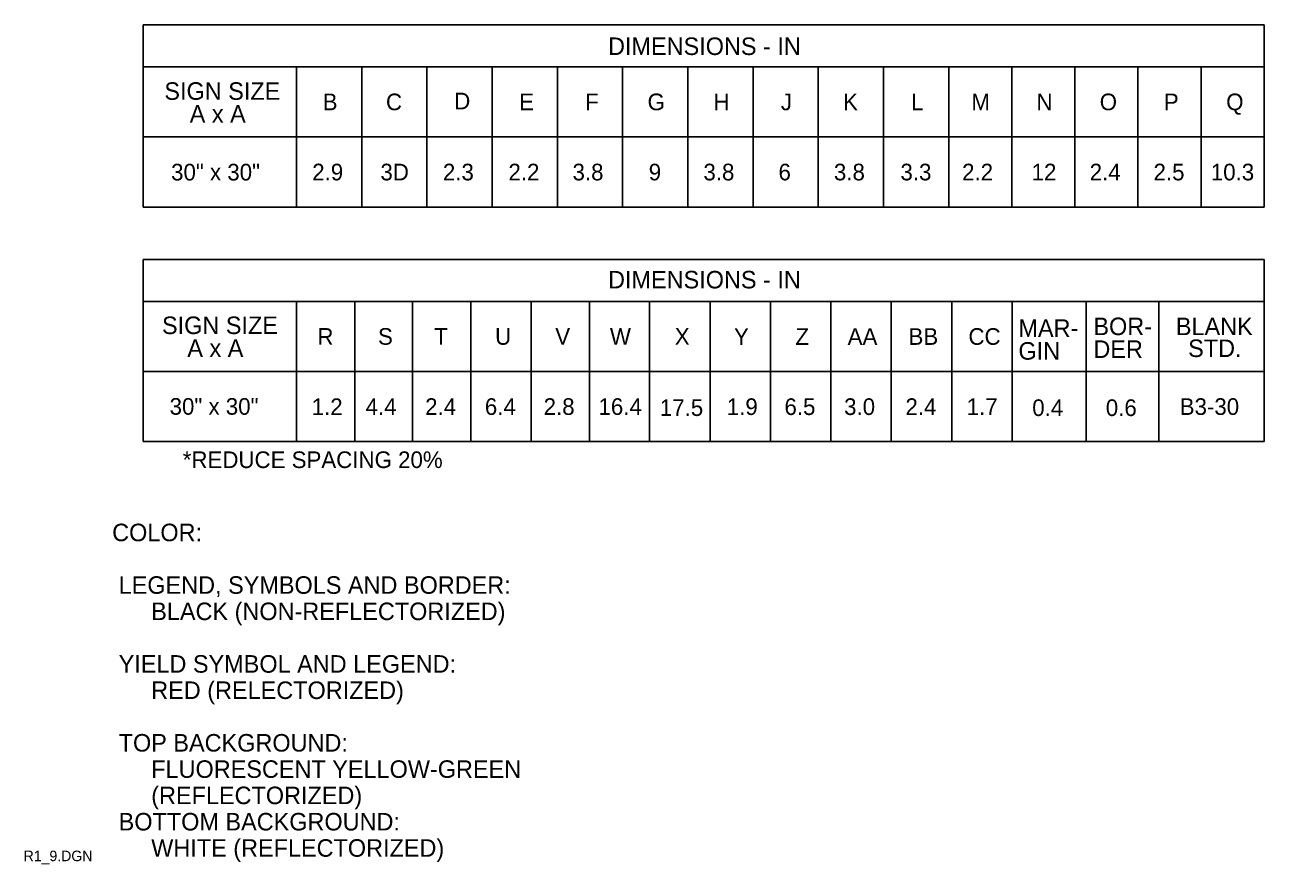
# Model space of a CAD drawing. Extents: x 0.013 to 0.193, y 0.003 to 0.259.
# Drawn here: x 0.0127 to 0.1894, y 0.0028 to 0.1225 of the extents above; entities that cross this region are included whole.
import ezdxf

# ---------------------------------------------------------------- set-up
doc = ezdxf.new("R2010")
doc.units = 0
doc.layers.add('1', color=7, linetype='Continuous')
doc.layers.add('3', color=7, linetype='Continuous')

msp = doc.modelspace()

# ---------------------------------------------------------------- linework, layer by layer
at = {"layer": '3'}
for p, q in [((0.02954535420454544, 0.12249248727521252), (0.02954535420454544, 0.09649248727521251)), ((0.02954535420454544, 0.1224891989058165), (0.1894203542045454, 0.1224891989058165)), ((0.1894203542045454, 0.12249248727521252), (0.1894203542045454, 0.09649248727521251)), ((0.02954535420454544, 0.1164891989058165), (0.1894203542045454, 0.1164891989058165)), ((0.05142035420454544, 0.1164891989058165), (0.05142035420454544, 0.09649248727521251)), ((0.06072035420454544, 0.1164891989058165), (0.06072035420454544, 0.09649248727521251)), ((0.07002035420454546, 0.1164891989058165), (0.07002035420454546, 0.09649248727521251)), ((0.07932035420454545, 0.1164891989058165), (0.07932035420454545, 0.09649248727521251)), ((0.08862035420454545, 0.1164891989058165), (0.08862035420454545, 0.09649248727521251)), ((0.09792035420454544, 0.1164891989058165), (0.09792035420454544, 0.09649248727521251)), ((0.10722035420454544, 0.1164891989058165), (0.10722035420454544, 0.09649248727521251)), ((0.11652035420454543, 0.1164891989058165), (0.11652035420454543, 0.09649248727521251)), ((0.12582035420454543, 0.1164891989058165), (0.12582035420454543, 0.09649248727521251)), ((0.13512035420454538, 0.1164891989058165), (0.13512035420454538, 0.09649248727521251)), ((0.14442035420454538, 0.1164891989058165), (0.14442035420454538, 0.09649248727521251)), ((0.1534203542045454, 0.1164891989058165), (0.1534203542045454, 0.09649248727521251)), ((0.1624203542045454, 0.1164891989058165), (0.1624203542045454, 0.09649248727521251)), ((0.1714203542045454, 0.1164891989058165), (0.1714203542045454, 0.09649248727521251)), ((0.18042035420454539, 0.1164891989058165), (0.18042035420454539, 0.09649248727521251)), ((0.02954535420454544, 0.10649248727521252), (0.1894203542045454, 0.10649248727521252)), ((0.02954535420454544, 0.09649248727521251), (0.1894203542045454, 0.09649248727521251)), ((0.02954535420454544, 0.08904164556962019), (0.02954535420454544, 0.06304493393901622)), ((0.02954535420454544, 0.08904164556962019), (0.1894203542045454, 0.08904164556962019)), ((0.1894203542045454, 0.06304493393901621), (0.1894203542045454, 0.08904164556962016)), ((0.029545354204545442, 0.08304164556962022), (0.1894203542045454, 0.08304164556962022)), ((0.051420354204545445, 0.08304164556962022), (0.051420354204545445, 0.06304493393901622)), ((0.05972318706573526, 0.08304164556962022), (0.05972318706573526, 0.06304493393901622)), ((0.06795264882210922, 0.08304164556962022), (0.06795264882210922, 0.06304493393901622)), ((0.07627276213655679, 0.08304164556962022), (0.07627276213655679, 0.06304493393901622)), ((0.08486483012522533, 0.08304164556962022), (0.08486483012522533, 0.06304493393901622)), ((0.09318494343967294, 0.08304164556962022), (0.09318494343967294, 0.06304493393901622)), ((0.10177417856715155, 0.08304164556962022), (0.10177417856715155, 0.06304493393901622)), ((0.11039067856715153, 0.08304164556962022), (0.11039067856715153, 0.06304493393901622)), ((0.11900717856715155, 0.08304164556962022), (0.11900717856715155, 0.06304493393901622)), ((0.12762367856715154, 0.08304164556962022), (0.12762367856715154, 0.06304493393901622)), ((0.13624017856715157, 0.08304164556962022), (0.13624017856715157, 0.06304493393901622)), ((0.14485667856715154, 0.08304164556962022), (0.14485667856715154, 0.06304493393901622)), ((0.15347317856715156, 0.08304164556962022), (0.15347317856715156, 0.06304493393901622)), ((0.1640348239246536, 0.08304164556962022), (0.1640348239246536, 0.06304493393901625)), ((0.17438738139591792, 0.08304164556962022), (0.17438738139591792, 0.06304493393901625)), ((0.02954535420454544, 0.07304493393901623), (0.1894203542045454, 0.07304493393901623)), ((0.02954535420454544, 0.06304493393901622), (0.1894203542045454, 0.06304493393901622))]:
    msp.add_line(p, q, dxfattribs=at)

# ---------------------------------------------------------------- texts
at = {"layer": '1'}
for s, height, p in [('COLOR:', 0.0024997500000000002, (0.025125, 0.048845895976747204)), (' LEGEND, SYMBOLS AND BORDER:', 0.0024997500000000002, (0.025125, 0.041346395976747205)), ('      BLACK (NON-REFLECTORIZED)', 0.0024997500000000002, (0.025125, 0.037596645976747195)), (' YIELD SYMBOL AND LEGEND:', 0.0024997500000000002, (0.025125, 0.0300971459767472)), ('      RED (RELECTORIZED)', 0.0024997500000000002, (0.025125, 0.026347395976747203)), (' TOP BACKGROUND:', 0.0024997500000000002, (0.025125, 0.018847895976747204)), ('      FLUORESCENT YELLOW-GREEN', 0.0024997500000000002, (0.025125, 0.015098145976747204)), ('      (REFLECTORIZED)', 0.0024997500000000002, (0.025125, 0.011348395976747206)), (' BOTTOM BACKGROUND:', 0.0024997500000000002, (0.025125, 0.007598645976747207)), ('      WHITE (REFLECTORIZED)', 0.0024997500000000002, (0.025125, 0.0038488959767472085)), ('R1_9.DGN', 0.0015, (0.0125, 0.003218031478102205))]:
    msp.add_text(s, height=height, dxfattribs=at).set_placement(p)
at = {"layer": '3'}
for s, height, p in [('DIMENSIONS - IN', 0.0024997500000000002, (0.09584596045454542, 0.11818332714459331)), ('SIGN SIZE', 0.0024997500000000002, (0.0325732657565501, 0.11179325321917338)), ('B', 0.0023752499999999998, (0.055148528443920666, 0.11030832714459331)), ('C', 0.0023752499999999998, (0.0641715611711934, 0.11030832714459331)), ('D', 0.0023752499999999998, (0.07390856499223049, 0.11043332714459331)), ('E', 0.0023752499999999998, (0.08315718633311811, 0.11030832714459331)), ('F', 0.0023752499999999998, (0.09257070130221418, 0.11030832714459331)), ('G', 0.0023752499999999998, (0.10147799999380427, 0.11030832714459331)), ('H', 0.0023752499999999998, (0.11086595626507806, 0.11030832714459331)), ('J', 0.0023752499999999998, (0.12048440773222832, 0.11030832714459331)), ('K', 0.0023752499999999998, (0.12935592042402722, 0.11030832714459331)), ('L', 0.0023752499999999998, (0.13905922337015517, 0.11030832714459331)), ('M', 0.0023752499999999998, (0.14765937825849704, 0.11030832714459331)), ('N', 0.0023752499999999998, (0.15693961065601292, 0.11030832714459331)), ('O', 0.0023752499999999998, (0.16596270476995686, 0.11030832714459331)), ('P', 0.0023752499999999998, (0.17510573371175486, 0.11030832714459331)), ('Q', 0.0023752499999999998, (0.18400144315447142, 0.11030832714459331)), ('A x A', 0.0024997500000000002, (0.0361850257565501, 0.10854350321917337)), ('30" x 30"', 0.0023752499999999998, (0.03353227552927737, 0.10028978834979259)), ('2.9', 0.0023752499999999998, (0.053657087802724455, 0.10030486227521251)), ('3D', 0.0023752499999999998, (0.06338366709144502, 0.10030486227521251)), ('2.3', 0.0023752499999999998, (0.07229183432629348, 0.10030486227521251)), ('2.2', 0.0023752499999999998, (0.08164169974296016, 0.10030486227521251)), ('3.8', 0.0023752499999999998, (0.09078044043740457, 0.10030486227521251)), ('9', 0.0023752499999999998, (0.10164516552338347, 0.10030486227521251)), ('3.8', 0.0023752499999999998, (0.1094465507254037, 0.10030486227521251)), ('6', 0.0023752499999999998, (0.12015084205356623, 0.10030486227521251)), ('3.8', 0.0023752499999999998, (0.1280575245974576, 0.10030486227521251)), ('3.3', 0.0023752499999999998, (0.13754204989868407, 0.10030486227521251)), ('2.2', 0.0023752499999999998, (0.14634046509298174, 0.10030486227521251)), ('12', 0.0023752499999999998, (0.15624574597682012, 0.10030486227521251)), ('2.4', 0.0023752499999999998, (0.16453746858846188, 0.10030486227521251)), ('2.5', 0.0023752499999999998, (0.17363709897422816, 0.10030486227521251)), ('10.3', 0.0023752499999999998, (0.1818081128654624, 0.10030486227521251)), ('DIMENSIONS - IN', 0.0024997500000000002, (0.09584596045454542, 0.08489645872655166)), ('SIGN SIZE', 0.0024997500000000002, (0.032235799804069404, 0.07838583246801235)), ('MAR-', 0.0024997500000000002, (0.1543670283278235, 0.07798577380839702)), ('BOR-', 0.0024997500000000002, (0.16506202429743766, 0.07823577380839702)), ('BLANK', 0.0024997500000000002, (0.17682254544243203, 0.07823577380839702)), ('R', 0.0023752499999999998, (0.05439148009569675, 0.076860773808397)), ('S', 0.0023752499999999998, (0.06303719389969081, 0.076860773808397)), ('T', 0.0023752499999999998, (0.07106280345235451, 0.076860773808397)), ('U', 0.0023752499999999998, (0.0797382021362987, 0.076860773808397)), ('V', 0.0023752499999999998, (0.08831857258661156, 0.076860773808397)), ('W', 0.0023752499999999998, (0.09610971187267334, 0.076860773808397)), ('X', 0.0023752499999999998, (0.10536407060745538, 0.076860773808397)), ('Y', 0.0023752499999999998, (0.11380277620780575, 0.07684963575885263)), ('Z', 0.0023752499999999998, (0.12256779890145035, 0.07684963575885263)), ('AA', 0.0023752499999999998, (0.13001408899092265, 0.07684963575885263)), ('BB', 0.0023752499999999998, (0.13869464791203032, 0.07684963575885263)), ('CC', 0.0023752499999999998, (0.1472411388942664, 0.07684963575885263)), ('A x A', 0.0024997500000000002, (0.035847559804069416, 0.07513608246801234)), ('GIN', 0.0024997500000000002, (0.1543670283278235, 0.07473577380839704)), ('DER', 0.0024997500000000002, (0.16506202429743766, 0.07498577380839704)), ('STD.', 0.0024997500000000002, (0.178572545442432, 0.07511077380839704)), ('30" x 30"', 0.0023752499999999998, (0.03331980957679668, 0.06688236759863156)), ('1.2', 0.0023752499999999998, (0.05357631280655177, 0.0668335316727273)), ('4.4', 0.0023752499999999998, (0.061263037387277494, 0.06685730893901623)), ('2.4', 0.0023752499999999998, (0.06975932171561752, 0.06685730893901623)), ('6.4', 0.0023752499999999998, (0.07827656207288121, 0.06685730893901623)), ('2.8', 0.0023752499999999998, (0.08665780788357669, 0.06685730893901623)), ('16.4', 0.0023752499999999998, (0.09448131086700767, 0.06685730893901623)), ('17.5', 0.0023752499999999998, (0.10323030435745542, 0.0667077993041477)), ('1.9', 0.0023752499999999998, (0.11277817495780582, 0.06684617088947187)), ('6.5', 0.0023752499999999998, (0.12100438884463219, 0.06684617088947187)), ('3.0', 0.0023752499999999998, (0.12951072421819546, 0.06684617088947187)), ('2.4', 0.0023752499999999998, (0.13826038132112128, 0.06684617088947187)), ('1.7', 0.0023752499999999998, (0.14698933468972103, 0.06684617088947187)), ('0.4', 0.0023752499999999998, (0.1563429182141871, 0.06669978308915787)), ('0.6', 0.0023752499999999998, (0.16682975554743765, 0.06669978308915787)), ('B3-30', 0.0023752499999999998, (0.1773676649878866, 0.06685730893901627)), ('*REDUCE SPACING 20%', 0.0023752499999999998, (0.035192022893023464, 0.05927946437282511))]:
    msp.add_text(s, height=height, dxfattribs=at).set_placement(p)

doc.saveas('drawing.dxf')
